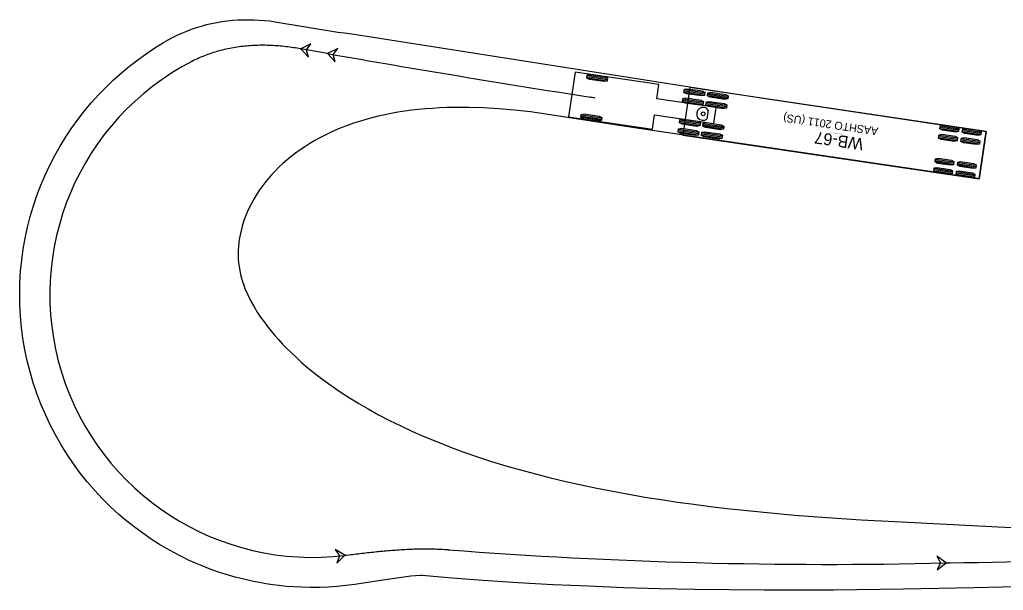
# Model space of a CAD drawing. Extents: x 2175591 to 2194071, y 76570 to 86955.
# Drawn here: x 2191921.3 to 2192095.4, y 86789.8 to 86890.9 of the extents above; entities that cross this region are included whole.
import ezdxf

# ---------------------------------------------------------------- set-up
doc = ezdxf.new("R2010")
doc.units = 0
doc.layers.add('C-UTIL-STRM-TEXT', color=7, linetype='Continuous')

msp = doc.modelspace()

# ---------------------------------------------------------------- linework, layer by layer
at = {"layer": 'C-UTIL-STRM-TEXT'}
for p, q in [((2191975.79, 86884.86), (2191971.05, 86885.7)), ((2192019.6, 86881.59), (2192018.43, 86873.67)), ((2192034.44, 86879.39), (2192019.6, 86881.59)), ((2192021.64, 86880.59), (2192025.27, 86880.05)), ((2192021.68, 86880.82), (2192025.3, 86880.28)), ((2192021.71, 86881.04), (2192025.34, 86880.51)), ((2192034.06, 86876.85), (2192034.44, 86879.39)), ((2192039.92, 86878.84), (2192038.67, 86870.43)), ((2192092.35, 86871.09), (2192039.92, 86878.84)), ((2192044.55, 86875.3), (2192034.06, 86876.85)), ((2192038.68, 86876.87), (2192042.31, 86876.33)), ((2192038.86, 86878.04), (2192042.48, 86877.51)), ((2192038.89, 86878.27), (2192042.52, 86877.74)), ((2192038.92, 86878.5), (2192042.55, 86877.96)), ((2192043.01, 86877.43), (2192046.64, 86876.89)), ((2192043.05, 86877.66), (2192046.67, 86877.12)), ((2192043.08, 86877.88), (2192046.71, 86877.35)), ((2192038.62, 86876.41), (2192042.24, 86875.88)), ((2192038.65, 86876.64), (2192042.28, 86876.1)), ((2192042.77, 86875.8), (2192046.4, 86875.26)), ((2192042.8, 86876.03), (2192046.43, 86875.49)), ((2192042.84, 86876.25), (2192046.46, 86875.72)), ((2192044.13, 86872.47), (2192044.55, 86875.3)), ((2192018.43, 86873.67), (2192033.27, 86871.48)), ((2192018.43, 86873.67), (2192018.43, 86873.67)), ((2192020.61, 86873.58), (2192024.24, 86873.05)), ((2192020.64, 86873.81), (2192024.27, 86873.27)), ((2192020.68, 86874.04), (2192024.3, 86873.5)), ((2192033.27, 86871.48), (2192033.65, 86874.02)), ((2192033.65, 86874.02), (2192044.13, 86872.47)), ((2192042.94, 86873.28), (2192043.18, 86874.87)), ((2192038.06, 86872.67), (2192041.69, 86872.13)), ((2192038.1, 86872.9), (2192041.72, 86872.36)), ((2192038.13, 86873.12), (2192041.76, 86872.59)), ((2192042.22, 86872.06), (2192045.84, 86871.52)), ((2192042.25, 86872.28), (2192045.88, 86871.75)), ((2192042.28, 86872.51), (2192045.91, 86871.97)), ((2192084.22, 86871.82), (2192087.48, 86871.34)), ((2192084.25, 86872.05), (2192087.52, 86871.57)), ((2192037.82, 86871.04), (2192041.45, 86870.5)), ((2192037.85, 86871.26), (2192041.48, 86870.73)), ((2192037.89, 86871.49), (2192041.52, 86870.95)), ((2192038.67, 86870.43), (2192091.1, 86862.68)), ((2192038.67, 86870.43), (2192038.67, 86870.43)), ((2192041.98, 86870.42), (2192045.6, 86869.89)), ((2192042.01, 86870.65), (2192045.64, 86870.11)), ((2192042.04, 86870.88), (2192045.67, 86870.34)), ((2192083.94, 86869.97), (2192087.21, 86869.48)), ((2192083.98, 86870.19), (2192087.24, 86869.71)), ((2192084.01, 86870.42), (2192087.27, 86869.94)), ((2192084.18, 86871.6), (2192087.45, 86871.11)), ((2192088.14, 86871.01), (2192091.41, 86870.53)), ((2192088.18, 86871.24), (2192091.44, 86870.76)), ((2192088.21, 86871.47), (2192091.47, 86870.98)), ((2192091.1, 86862.68), (2192092.35, 86871.09)), ((2192087.9, 86869.38), (2192091.16, 86868.9)), ((2192087.93, 86869.61), (2192091.2, 86869.12)), ((2192087.97, 86869.83), (2192091.23, 86869.35)), ((2192083.32, 86865.73), (2192086.58, 86865.25)), ((2192083.35, 86865.95), (2192086.61, 86865.47)), ((2192083.38, 86866.18), (2192086.65, 86865.7)), ((2192087.27, 86865.14), (2192090.54, 86864.66)), ((2192087.31, 86865.37), (2192090.57, 86864.89)), ((2192087.34, 86865.6), (2192090.61, 86865.11)), ((2192083.08, 86864.1), (2192086.34, 86863.61)), ((2192083.11, 86864.32), (2192086.37, 86863.84)), ((2192083.14, 86864.55), (2192086.41, 86864.07)), ((2192087.03, 86863.51), (2192090.3, 86863.03)), ((2192087.07, 86863.74), (2192090.33, 86863.25)), ((2192087.1, 86863.96), (2192090.36, 86863.48))]:
    msp.add_line(p, q, dxfattribs=at)
for points in [[(2192102.66, 86790.54), (2192090.21, 86790.24), (2192077.72, 86790.01), (2192065.34, 86789.85), (2192059.33, 86789.82), (2192053.11, 86789.83), (2192046.9, 86789.88), (2192040.7, 86789.97), (2192034.49, 86790.11), (2192028.23, 86790.29), (2192021.97, 86790.53), (2192015.71, 86790.82), (2192009.48, 86791.17), (2192003.27, 86791.58), (2191997.1, 86792.06), (2191992.53, 86792.46), (2191992.15, 86792.47), (2191990.52, 86792.31), (2191988.88, 86792.11), (2191985.58, 86791.64), (2191980.61, 86790.86), (2191978.99, 86790.65), (2191977.41, 86790.49), (2191975.86, 86790.38), (2191974.34, 86790.33), (2191972.7, 86790.32), (2191971.26, 86790.35), (2191969.86, 86790.42), (2191968.5, 86790.52), (2191967.18, 86790.66), (2191966.08, 86790.79), (2191964.85, 86790.98), (2191963.71, 86791.18), (2191962.64, 86791.39), (2191960.93, 86791.77), (2191959.44, 86792.16), (2191957.83, 86792.62), (2191956.32, 86793.11), (2191954.68, 86793.71), (2191953.56, 86794.15), (2191952.42, 86794.63), (2191951.3, 86795.13), (2191949.94, 86795.79), (2191948.58, 86796.5), (2191947.26, 86797.23), (2191946.03, 86797.96), (2191944.57, 86798.89), (2191943.06, 86799.92), (2191941.53, 86801.06), (2191939.97, 86802.3), (2191938.85, 86803.27), (2191937.37, 86804.62), (2191935.94, 86806.03), (2191934.57, 86807.5), (2191933.25, 86809.02), (2191932, 86810.59), (2191930.8, 86812.21), (2191929.67, 86813.88), (2191928.61, 86815.59), (2191927.61, 86817.34), (2191926.68, 86819.12), (2191925.82, 86820.94), (2191925.03, 86822.8), (2191924.32, 86824.68), (2191923.68, 86826.58), (2191923.11, 86828.51), (2191922.62, 86830.45), (2191922.2, 86832.42), (2191921.86, 86834.39), (2191921.6, 86836.37), (2191921.42, 86838.36), (2191921.31, 86840.35), (2191921.28, 86842.34), (2191921.32, 86844.33), (2191921.44, 86846.31), (2191921.64, 86848.28), (2191921.91, 86850.24), (2191922.25, 86852.18), (2191922.67, 86854.1), (2191923.16, 86856), (2191923.71, 86857.88), (2191924.34, 86859.73), (2191925.03, 86861.55), (2191925.79, 86863.33), (2191926.61, 86865.08), (2191927.5, 86866.8), (2191928.44, 86868.47), (2191929.44, 86870.1), (2191930.5, 86871.69), (2191931.61, 86873.24), (2191932.78, 86874.74), (2191933.99, 86876.18), (2191935.25, 86877.58), (2191936.56, 86878.93), (2191937.91, 86880.22), (2191939.3, 86881.46), (2191940.72, 86882.65), (2191942.18, 86883.78), (2191943.68, 86884.85), (2191945.21, 86885.86), (2191946.76, 86886.82), (2191947.55, 86887.28), (2191948.35, 86887.71), (2191949.16, 86888.12), (2191949.99, 86888.51), (2191950.84, 86888.86), (2191951.69, 86889.19), (2191952.56, 86889.48), (2191953.45, 86889.75), (2191954.34, 86889.99), (2191955.24, 86890.2), (2191956.15, 86890.39), (2191957.07, 86890.54), (2191958, 86890.66), (2191958.94, 86890.76), (2191959.87, 86890.83), (2191960.82, 86890.86), (2191961.77, 86890.87), (2191962.72, 86890.86), (2191963.67, 86890.81), (2191964.62, 86890.74), (2191965.58, 86890.64), (2191966.53, 86890.51), (2191977.62, 86888.65), (2191979.22, 86888.46), (2191980.82, 86888.25), (2192041.02, 86878.8), (2192053.28, 86876.91), (2192065.58, 86875.06), (2192092.35, 86871.09), (2192091.1, 86862.68), (2192090.82, 86862.72), (2192090.82, 86862.72)], [(2191971.05, 86885.7), (2191970.72, 86885.75), (2191970.39, 86885.81), (2191970.06, 86885.86), (2191969.73, 86885.91), (2191969.4, 86885.96), (2191969.07, 86886), (2191968.74, 86886.05), (2191968.41, 86886.09), (2191968.08, 86886.12), (2191967.75, 86886.16), (2191967.42, 86886.19), (2191967.09, 86886.22), (2191966.75, 86886.24), (2191966.42, 86886.26), (2191966.09, 86886.28), (2191965.75, 86886.3), (2191965.42, 86886.31), (2191965.09, 86886.32), (2191964.75, 86886.33), (2191964.42, 86886.33), (2191964.09, 86886.33), (2191963.75, 86886.33), (2191963.42, 86886.32), (2191963.09, 86886.31), (2191962.76, 86886.3), (2191962.42, 86886.28), (2191962.09, 86886.26), (2191961.76, 86886.24), (2191961.43, 86886.21), (2191961.09, 86886.18), (2191960.76, 86886.14), (2191960.43, 86886.1), (2191960.1, 86886.06), (2191959.77, 86886.01), (2191959.44, 86885.96), (2191959.11, 86885.91), (2191958.78, 86885.85), (2191958.46, 86885.79), (2191958.13, 86885.72), (2191957.8, 86885.65), (2191957.48, 86885.58), (2191957.15, 86885.5), (2191956.83, 86885.42), (2191956.51, 86885.33), (2191956.19, 86885.24), (2191955.87, 86885.14), (2191955.55, 86885.05), (2191955.23, 86884.94), (2191954.92, 86884.84), (2191954.6, 86884.72), (2191954.29, 86884.61), (2191953.98, 86884.49), (2191953.67, 86884.36), (2191953.36, 86884.23), (2191953.06, 86884.1), (2191952.75, 86883.96), (2191952.45, 86883.82), (2191952.15, 86883.68), (2191951.86, 86883.53)], [(2192022.97, 86877.04), (2192022.64, 86877.09), (2192022.31, 86877.14)], [(2192090.82, 86862.72), (2192041.59, 86870), (2192030.08, 86871.71), (2192018.25, 86873.54), (2192011.71, 86874.56), (2192008.88, 86874.85), (2192006.1, 86875.08), (2192003.4, 86875.24), (2192000.76, 86875.32), (2191999.46, 86875.33), (2191998.16, 86875.33), (2191996.87, 86875.3), (2191995.6, 86875.25), (2191994.34, 86875.17), (2191993.09, 86875.08), (2191991.86, 86874.96), (2191990.63, 86874.83), (2191989.43, 86874.66), (2191988.24, 86874.48), (2191987.06, 86874.27), (2191985.9, 86874.04), (2191984.76, 86873.78), (2191983.64, 86873.5), (2191982.53, 86873.2), (2191981.44, 86872.87), (2191980.38, 86872.52), (2191979.33, 86872.15), (2191978.3, 86871.76), (2191977.3, 86871.34), (2191976.32, 86870.9), (2191975.36, 86870.44), (2191974.42, 86869.96), (2191973.51, 86869.45), (2191972.62, 86868.93), (2191971.76, 86868.38), (2191970.93, 86867.82), (2191970.12, 86867.24), (2191969.34, 86866.64), (2191968.58, 86866.02), (2191967.86, 86865.39), (2191967.16, 86864.74), (2191966.5, 86864.07), (2191965.86, 86863.39), (2191965.26, 86862.7), (2191964.68, 86862), (2191964.14, 86861.28), (2191963.63, 86860.55), (2191963.15, 86859.82), (2191962.7, 86859.08), (2191962.29, 86858.33), (2191961.91, 86857.57), (2191961.57, 86856.81), (2191961.25, 86856.05), (2191960.97, 86855.28), (2191960.73, 86854.52), (2191960.52, 86853.75), (2191960.34, 86852.99), (2191960.2, 86852.23), (2191960.09, 86851.48), (2191960.01, 86850.73), (2191959.96, 86849.98), (2191959.95, 86849.25), (2191959.97, 86848.53), (2191960.03, 86847.82), (2191960.11, 86847.12), (2191960.22, 86846.43), (2191960.37, 86845.77), (2191960.53, 86845.11), (2191960.73, 86844.48), (2191960.94, 86843.86), (2191961.16, 86843.26), (2191961.66, 86842.12), (2191962.2, 86841.05), (2191962.76, 86840.05), (2191963.34, 86839.1), (2191963.93, 86838.2), (2191964.54, 86837.35), (2191965.15, 86836.53), (2191965.78, 86835.74), (2191966.42, 86834.97), (2191967.08, 86834.23), (2191967.82, 86833.42), (2191968.55, 86832.66), (2191969.37, 86831.85), (2191970.19, 86831.08), (2191971.18, 86830.18), (2191972.3, 86829.22), (2191973.55, 86828.21), (2191974.94, 86827.14), (2191976.41, 86826.07), (2191977.98, 86824.99), (2191979.64, 86823.92), (2191981.33, 86822.88), (2191982.96, 86821.94), (2191984.8, 86820.92), (2191986.73, 86819.92), (2191988.72, 86818.94), (2191990.81, 86817.96), (2191992.98, 86817.01), (2191995.21, 86816.09), (2191997.52, 86815.19), (2191999.89, 86814.31), (2192002.32, 86813.47), (2192004.81, 86812.66), (2192007.34, 86811.88), (2192009.93, 86811.13), (2192012.56, 86810.42), (2192015.23, 86809.74), (2192017.94, 86809.09), (2192020.68, 86808.48), (2192023.45, 86807.89), (2192026.25, 86807.35), (2192029.08, 86806.83), (2192031.92, 86806.34), (2192034.8, 86805.88), (2192037.69, 86805.45), (2192040.6, 86805.05), (2192043.54, 86804.67), (2192046.49, 86804.32), (2192049.46, 86803.99), (2192052.43, 86803.69), (2192055.41, 86803.41), (2192058.41, 86803.15), (2192064.19, 86802.7), (2192070.21, 86802.31), (2192076.16, 86801.98), (2192121.98, 86799.62)], [(2191978.86, 86796.02), (2191979.19, 86796.06), (2191979.52, 86796.1), (2191979.85, 86796.14), (2191980.18, 86796.18), (2191980.51, 86796.22), (2191980.84, 86796.26), (2191981.17, 86796.3), (2191981.5, 86796.34), (2191981.83, 86796.38), (2191982.17, 86796.42), (2191982.5, 86796.46), (2191982.83, 86796.49), (2191983.16, 86796.53), (2191983.49, 86796.57), (2191983.82, 86796.6), (2191984.15, 86796.64), (2191984.49, 86796.67), (2191984.82, 86796.7), (2191985.15, 86796.74), (2191985.48, 86796.77), (2191985.81, 86796.8), (2191986.14, 86796.83), (2191986.48, 86796.86), (2191986.81, 86796.89), (2191987.14, 86796.91), (2191987.47, 86796.94), (2191987.81, 86796.96), (2191988.14, 86796.99), (2191988.47, 86797.01), (2191988.8, 86797.03), (2191989.14, 86797.05), (2191989.47, 86797.07), (2191989.8, 86797.09), (2191990.14, 86797.1), (2191990.47, 86797.11), (2191990.8, 86797.13), (2191991.13, 86797.14), (2191991.47, 86797.15), (2191991.8, 86797.16), (2191992.13, 86797.16), (2191992.47, 86797.17), (2191992.8, 86797.17), (2191993.13, 86797.17), (2191993.47, 86797.17), (2191993.8, 86797.16), (2191994.13, 86797.16), (2191994.47, 86797.15), (2191994.8, 86797.14), (2191995.13, 86797.13), (2191995.47, 86797.12), (2191995.8, 86797.1), (2191996.13, 86797.09), (2191996.47, 86797.07), (2191996.8, 86797.04), (2191997.13, 86797.02)], [(2192085.25, 86794.69), (2192085.58, 86794.69), (2192085.91, 86794.7)]]:
    msp.add_lwpolyline(points, dxfattribs=at)
for points in [[(2191971.05, 86885.7), (2191972.4, 86884.22), (2191972.03, 86885.52), (2191972.82, 86886.62)], [(2191975.79, 86884.86), (2191977.14, 86883.39), (2191976.78, 86884.69), (2191977.57, 86885.79)], [(2192021.64, 86880.53), (2192021.72, 86881.1), (2192022.25, 86881.19), (2192024.86, 86880.81), (2192025.35, 86880.56), (2192025.26, 86880), (2192024.73, 86879.9), (2192022.12, 86880.29)], [(2192038.85, 86877.99), (2192038.93, 86878.55), (2192039.47, 86878.65), (2192042.08, 86878.26), (2192042.56, 86878.02), (2192042.48, 86877.45), (2192041.94, 86877.36), (2192039.33, 86877.74)], [(2192038.61, 86876.36), (2192038.69, 86876.92), (2192039.22, 86877.02), (2192041.84, 86876.63), (2192042.32, 86876.39), (2192042.23, 86875.82), (2192041.7, 86875.72), (2192039.09, 86876.11)], [(2192043, 86877.37), (2192043.09, 86877.94), (2192043.62, 86878.04), (2192046.23, 86877.65), (2192046.71, 86877.4), (2192046.63, 86876.84), (2192046.1, 86876.74), (2192043.49, 86877.13)], [(2192042.76, 86875.74), (2192042.85, 86876.31), (2192043.38, 86876.4), (2192045.99, 86876.02), (2192046.47, 86875.77), (2192046.39, 86875.21), (2192045.86, 86875.11), (2192043.24, 86875.5)], [(2192020.6, 86873.53), (2192020.68, 86874.09), (2192021.22, 86874.19), (2192023.83, 86873.8), (2192024.31, 86873.56), (2192024.23, 86872.99), (2192023.69, 86872.89), (2192021.08, 86873.28)], [(2192037.81, 86870.98), (2192037.9, 86871.55), (2192038.43, 86871.64), (2192041.04, 86871.26), (2192041.52, 86871.01), (2192041.44, 86870.45), (2192040.91, 86870.35), (2192038.3, 86870.74)], [(2192038.05, 86872.61), (2192038.14, 86873.18), (2192038.67, 86873.27), (2192041.28, 86872.89), (2192041.76, 86872.64), (2192041.68, 86872.08), (2192041.15, 86871.98), (2192038.54, 86872.37)], [(2192042.21, 86872), (2192042.29, 86872.57), (2192042.83, 86872.66), (2192045.44, 86872.27), (2192045.92, 86872.03), (2192045.84, 86871.46), (2192045.3, 86871.37), (2192042.69, 86871.75)], [(2192084.18, 86871.54), (2192084.26, 86872.11), (2192084.74, 86872.21), (2192087.09, 86871.86), (2192087.52, 86871.62), (2192087.44, 86871.06), (2192086.96, 86870.96), (2192084.61, 86871.3)], [(2192088.13, 86870.96), (2192088.22, 86871.52), (2192088.7, 86871.63), (2192091.05, 86871.28), (2192091.48, 86871.04), (2192091.4, 86870.47), (2192090.92, 86870.37), (2192088.57, 86870.72)], [(2192041.97, 86870.37), (2192042.05, 86870.93), (2192042.58, 86871.03), (2192045.2, 86870.64), (2192045.68, 86870.4), (2192045.59, 86869.83), (2192045.06, 86869.74), (2192042.45, 86870.12)], [(2192083.93, 86869.91), (2192084.02, 86870.47), (2192084.5, 86870.58), (2192086.85, 86870.23), (2192087.28, 86869.99), (2192087.2, 86869.43), (2192086.72, 86869.32), (2192084.37, 86869.67)], [(2192087.89, 86869.32), (2192087.98, 86869.89), (2192088.46, 86869.99), (2192090.81, 86869.65), (2192091.24, 86869.41), (2192091.16, 86868.84), (2192090.67, 86868.74), (2192088.32, 86869.09)], [(2192083.07, 86864.04), (2192083.15, 86864.61), (2192083.63, 86864.71), (2192085.98, 86864.36), (2192086.42, 86864.12), (2192086.33, 86863.56), (2192085.85, 86863.45), (2192083.5, 86863.8)], [(2192083.31, 86865.67), (2192083.39, 86866.24), (2192083.87, 86866.34), (2192086.22, 86865.99), (2192086.66, 86865.75), (2192086.57, 86865.19), (2192086.09, 86865.09), (2192083.74, 86865.43)], [(2192087.27, 86865.09), (2192087.35, 86865.65), (2192087.83, 86865.76), (2192090.18, 86865.41), (2192090.61, 86865.17), (2192090.53, 86864.6), (2192090.05, 86864.5), (2192087.7, 86864.85)], [(2192087.02, 86863.45), (2192087.11, 86864.02), (2192087.59, 86864.12), (2192089.94, 86863.78), (2192090.37, 86863.54), (2192090.29, 86862.97), (2192089.81, 86862.87), (2192087.46, 86863.22)], [(2191978.86, 86796.02), (2191977.13, 86797.03), (2191977.86, 86795.9), (2191977.43, 86794.61)], [(2192085.25, 86794.69), (2192083.63, 86795.86), (2192084.25, 86794.66), (2192083.69, 86793.43)]]:
    msp.add_lwpolyline(points, close=True, dxfattribs=at)
for centre, radius in [((2191971.05, 86885.7), 0.0417), ((2191971.05, 86885.7), 0.0417), ((2191975.79, 86884.86), 0.0417), ((2191975.79, 86884.86), 0.0417), ((2191951.86, 86883.53), 0.0417), ((2191951.86, 86883.53), 0.0417), ((2192022.31, 86877.14), 0.0417), ((2192022.31, 86877.14), 0.0417), ((2192022.97, 86877.04), 0.0417), ((2192042.26, 86874.19), 0.34), ((2191997.13, 86797.02), 0.0417), ((2191997.13, 86797.02), 0.0417), ((2191978.86, 86796.02), 0.0417), ((2191978.86, 86796.02), 0.0417), ((2192085.25, 86794.69), 0.0417), ((2192085.25, 86794.69), 0.0417), ((2192085.91, 86794.7), 0.0417), ((2192085.91, 86794.7), 0.0417)]:
    msp.add_circle(centre, radius, dxfattribs=at)
for centre, radius, start, end in [((2192401.24, 89305.15), 2457.39, 260.03015, 261.12967), ((2191973.13, 86842.17), 46.51, 117.2278, 277.0677), ((2192042.26, 86874.19), 1.14, 36.5917, 306.5917), ((2192064.01, 87657.5), 863.08, 265.55562, 271.40997), ((2192061.95, 88612.05), 1817.51, 270.75542, 272.02321)]:
    msp.add_arc(centre, radius, start, end, dxfattribs=at)

# ---------------------------------------------------------------- texts
for s, height, p in [('AASHTO 2011 (US)', 1.4167, (2192073.31, 86871.76)), ('WB-67', 2.125, (2192070.74, 86869.81)), ('(c) 2019 Transoft Solutions, Inc. All rights reserved.', 0.085, (2192067.23, 86870.55))]:
    msp.add_text(s, height=height, rotation=171.5917, dxfattribs=at).set_placement(p)

doc.saveas('drawing.dxf')
